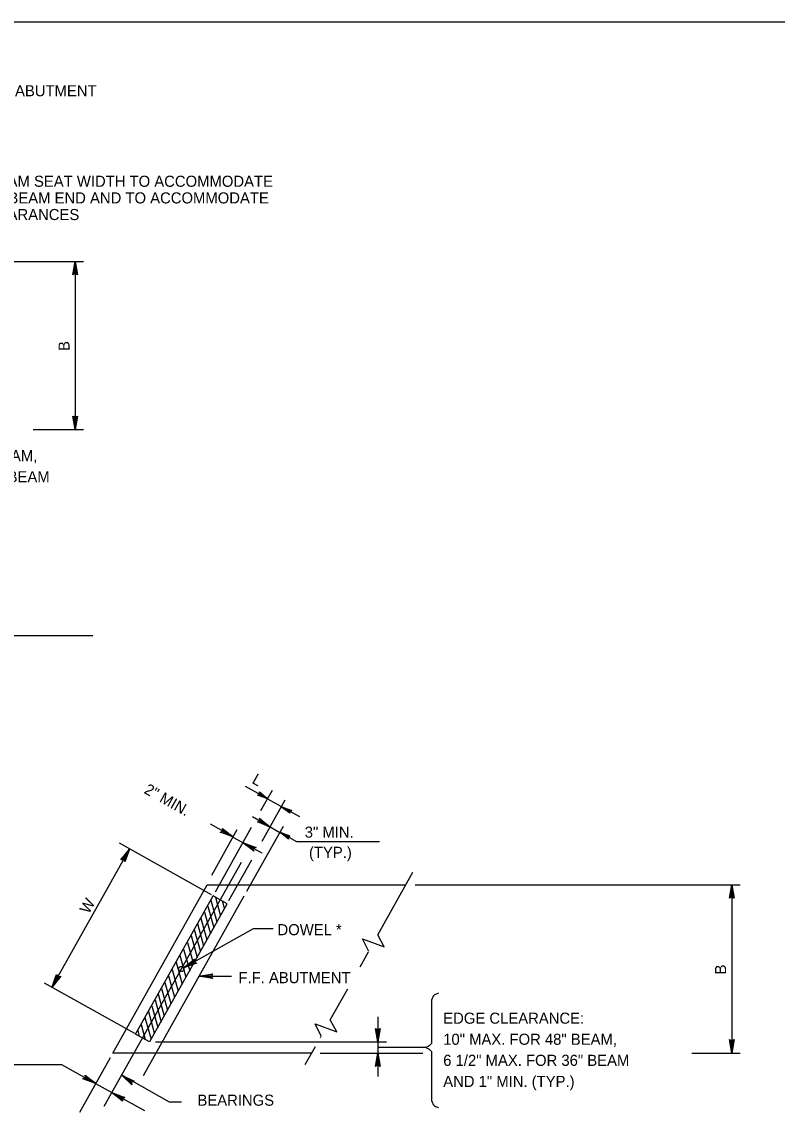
# Model space of a CAD drawing. Extents: x 639028 to 640031, y 298558 to 299746.
# Drawn here: x 639392.4 to 639596.7, y 298842.4 to 299137.3 of the extents above; entities that cross this region are included whole.
import ezdxf

# ---------------------------------------------------------------- set-up
doc = ezdxf.new("R2010")
doc.units = 0
doc.layers.add('1', color=7, linetype='Continuous')

msp = doc.modelspace()

# ---------------------------------------------------------------- linework, layer by layer
at = {"layer": '1'}
for p, q in [((639067.87, 299137.33), (639853.87, 299137.33)), ((639362.68, 299072.53), (639409.1, 299072.53)), ((639406.83, 299072.53), (639406.83, 299027.03)), ((639395.46, 299027.03), (639409.1, 299027.03)), ((639250.86, 298971.38), (639411.63, 298971.38)), ((639458.91, 298927.15), (639452.91, 298930.52)), ((639457.06, 298923.97), (639460.16, 298929.52)), ((639457.4, 298915.71), (639463.66, 298926.9)), ((639458.83, 298927.13), (639467.5, 298922.37)), ((639449.54, 298916.9), (639443.44, 298920.27)), ((639462.17, 298918), (639454.79, 298922.27)), ((639443.79, 298906.52), (639450.66, 298918.9)), ((639444.79, 298902.02), (639454.53, 298919.45)), ((639453.29, 298902.15), (639463.16, 298919.77)), ((639466.79, 298915.52), (639462.16, 298918.15)), ((639443.66, 298901.15), (639418.79, 298915.15)), ((639449.5, 298916.81), (639457.29, 298912.52)), ((639489.11, 298915.52), (639466.79, 298915.52)), ((639400.54, 298876.15), (639421.54, 298913.52)), ((639414.66, 298844.02), (639451.79, 298910.02)), ((639448.41, 298899.65), (639454.56, 298910.63)), ((639488.71, 298890.34), (639498.2, 298907.28)), ((639417.04, 298858.4), (639442.54, 298903.9)), ((639442.54, 298903.9), (639496.3, 298903.9)), ((639498.77, 298903.9), (639586.69, 298903.9)), ((639584.42, 298903.9), (639584.42, 298858.4)), ((639423.16, 298863.52), (639444.16, 298900.9)), ((639425.33, 298852.32), (639452.54, 298900.9)), ((639443.54, 298899.77), (639445.16, 298893.9)), ((639444.16, 298900.9), (639444.29, 298901.02)), ((639447.91, 298898.77), (639444.16, 298900.9)), ((639444.79, 298900.52), (639446.04, 298895.77)), ((639446.66, 298899.4), (639447.16, 298897.52)), ((639427.04, 298861.52), (639447.91, 298898.77)), ((639441.79, 298896.52), (639443.41, 298890.65)), ((639442.66, 298898.15), (639444.29, 298892.27)), ((639439.91, 298893.4), (639441.54, 298887.4)), ((639440.79, 298894.9), (639442.41, 298889.02)), ((639436.13, 298881.47), (639455.03, 298892.06)), ((639439.04, 298891.77), (639440.66, 298886.15)), ((639455.03, 298892.06), (639460.37, 298892.06)), ((639437.16, 298888.27), (639438.79, 298882.4)), ((639438.16, 298890.15), (639439.79, 298884.27)), ((639435.16, 298884.9), (639436.79, 298878.9)), ((639436.16, 298886.52), (639437.79, 298880.65)), ((639483.87, 298881.71), (639486.15, 298885.79)), ((639434.16, 298883.02), (639435.79, 298877.02)), ((639432.04, 298879.27), (639433.66, 298873.52)), ((639433.04, 298881.02), (639434.66, 298875.15)), ((639440.37, 298879.17), (639449.12, 298879.17)), ((639422.91, 298863.65), (639398.54, 298877.27)), ((639430.16, 298875.9), (639431.79, 298870.02)), ((639431.04, 298877.52), (639432.66, 298871.77)), ((639475.83, 298867.37), (639480.55, 298875.78)), ((639428.41, 298872.77), (639430.04, 298866.77)), ((639429.29, 298874.4), (639430.91, 298868.4)), ((639503.38, 298873.18), (639503.22, 298872.72)), ((639503.22, 298872.72), (639503.22, 298860.99)), ((639503.53, 298873.49), (639503.38, 298873.18)), ((639503.69, 298873.8), (639503.53, 298873.49)), ((639503.84, 298873.96), (639503.69, 298873.8)), ((639504, 298874.11), (639503.84, 298873.96)), ((639504.31, 298874.27), (639504, 298874.11)), ((639504.62, 298874.43), (639504.31, 298874.27)), ((639505.08, 298874.58), (639504.62, 298874.43)), ((639427.54, 298871.15), (639429.16, 298865.27)), ((639425.66, 298868.02), (639427.41, 298862.15)), ((639426.66, 298869.65), (639428.16, 298863.9)), ((639488.66, 298868.15), (639488.66, 298861.4)), ((639423.79, 298864.52), (639424.16, 298862.9)), ((639424.66, 298866.15), (639425.79, 298862.02)), ((639426.91, 298861.4), (639423.16, 298863.52)), ((639428.54, 298861.4), (639491.04, 298861.4)), ((639473.17, 298862.61), (639473.35, 298862.94)), ((639488.66, 298861.68), (639488.66, 298852.02)), ((639503.22, 298860.99), (639502.91, 298860.68)), ((639470.8, 298858.4), (639417.04, 298858.4)), ((639469.07, 298855.3), (639471.8, 298860.17)), ((639473.13, 298858.4), (639500.83, 298858.4)), ((639501.66, 298859.9), (639488.66, 298859.9)), ((639502.29, 298860.21), (639501.66, 298859.9)), ((639501.66, 298859.9), (639502.6, 298859.43)), ((639502.6, 298860.36), (639502.29, 298860.21)), ((639502.91, 298860.68), (639502.6, 298860.36)), ((639502.6, 298859.43), (639502.75, 298859.28)), ((639502.75, 298859.28), (639503.06, 298858.97)), ((639503.06, 298858.97), (639503.22, 298858.81)), ((639503.22, 298858.81), (639503.22, 298845.54)), ((639573.64, 298858.4), (639586.69, 298858.4)), ((639403.23, 298855.21), (639333.43, 298855.21)), ((639412.39, 298850.07), (639403.23, 298855.21)), ((639408.04, 298842.4), (639416.41, 298857.15)), ((639432.29, 298845.15), (639419.41, 298852.4)), ((639425.7, 298842.75), (639412.39, 298850.07)), ((639435.54, 298845.15), (639432.29, 298845.15)), ((639503.22, 298845.54), (639503.38, 298845.07)), ((639503.38, 298845.07), (639503.53, 298844.76)), ((639503.53, 298844.76), (639503.69, 298844.45)), ((639503.69, 298844.45), (639503.84, 298844.29)), ((639503.84, 298844.29), (639504, 298844.14)), ((639504, 298844.14), (639504.31, 298843.98)), ((639504.31, 298843.98), (639504.62, 298843.83)), ((639504.62, 298843.83), (639505.08, 298843.67))]:
    msp.add_line(p, q, dxfattribs=at)
for points in [[(639406.45, 299069.03), (639406.58, 299069.15), (639406.83, 299072.53), (639406.45, 299069.03), (639406.2, 299068.9), (639406.83, 299072.53), (639406.95, 299069.15), (639407.2, 299069.03), (639406.83, 299072.53), (639407.45, 299068.9), (639407.2, 299069.03)], [(639407.2, 299030.53), (639407.08, 299030.4), (639406.83, 299027.03), (639407.2, 299030.53), (639407.45, 299030.65), (639406.83, 299027.03), (639406.7, 299030.4), (639406.45, 299030.53), (639406.83, 299027.03), (639406.2, 299030.65), (639406.45, 299030.53)], [(639456.66, 298928.77), (639456.66, 298928.65), (639458.91, 298927.15), (639456.66, 298928.77), (639456.66, 298929.02), (639458.91, 298927.15), (639456.54, 298928.4), (639456.41, 298928.27), (639458.91, 298927.15), (639456.16, 298928.15), (639456.41, 298928.27)], [(639464.91, 298923.4), (639464.91, 298923.65), (639462.66, 298925.02), (639464.91, 298923.4), (639464.91, 298923.27), (639462.66, 298925.02), (639465.04, 298923.9), (639465.16, 298924.02), (639462.66, 298925.02), (639465.41, 298924.02), (639465.16, 298924.02)], [(639456.79, 298921.65), (639456.79, 298921.4), (639459.54, 298919.52), (639456.79, 298921.65), (639456.66, 298921.9), (639459.54, 298919.52), (639456.54, 298921.02), (639456.41, 298920.9), (639459.54, 298919.52), (639456.16, 298920.9), (639456.41, 298920.9)], [(639446.66, 298918.9), (639446.66, 298918.65), (639449.54, 298916.9), (639446.66, 298918.9), (639446.66, 298919.15), (639449.54, 298916.9), (639446.54, 298918.4), (639446.29, 298918.15), (639449.54, 298916.9), (639446.04, 298918.15), (639446.29, 298918.15)], [(639464.41, 298916.52), (639464.41, 298916.65), (639462.16, 298918.15), (639464.41, 298916.52), (639464.54, 298916.27), (639462.16, 298918.15), (639464.54, 298916.9), (639464.79, 298917.02), (639462.16, 298918.15), (639464.91, 298917.15), (639464.79, 298917.02)], [(639455.04, 298913.27), (639455.04, 298913.52), (639452.29, 298915.27), (639455.04, 298913.27), (639455.16, 298913.02), (639452.29, 298915.27), (639455.29, 298913.77), (639455.54, 298914.02), (639452.29, 298915.27), (639455.79, 298914.02), (639455.54, 298914.02)], [(639419.41, 298910.77), (639419.66, 298910.77), (639421.54, 298913.52), (639419.41, 298910.77), (639419.16, 298910.65), (639421.54, 298913.52), (639420.04, 298910.52), (639420.16, 298910.27), (639421.54, 298913.52), (639420.29, 298910.15), (639420.16, 298910.27)], [(639584.04, 298900.4), (639584.17, 298900.52), (639584.42, 298903.9), (639584.04, 298900.4), (639583.79, 298900.27), (639584.42, 298903.9), (639584.54, 298900.52), (639584.79, 298900.4), (639584.42, 298903.9), (639585.04, 298900.27), (639584.79, 298900.4)], [(639486.24, 298885.89), (639484.58, 298889.31), (639490.44, 298887.16), (639488.71, 298890.34)], [(639439.38, 298882.8), (639439.16, 298882.96), (639436.13, 298881.47), (639439.38, 298882.8), (639439.72, 298882.7), (639436.13, 298881.47), (639438.98, 298883.29), (639439.03, 298883.46), (639436.13, 298881.47), (639439.13, 298883.8), (639439.03, 298883.46)], [(639402.66, 298879.02), (639402.41, 298879.02), (639400.54, 298876.15), (639402.66, 298879.02), (639402.91, 298879.15), (639400.54, 298876.15), (639402.04, 298879.15), (639401.91, 298879.4), (639400.54, 298876.15), (639401.79, 298879.65), (639401.91, 298879.4)], [(639443.87, 298878.79), (639443.74, 298879.04), (639440.37, 298879.17), (639443.87, 298878.79), (639443.99, 298878.54), (639440.37, 298879.17), (639443.74, 298879.29), (639443.87, 298879.54), (639440.37, 298879.17), (639443.99, 298879.79), (639443.87, 298879.54)], [(639473.35, 298862.94), (639471.71, 298866.32), (639477.57, 298864.17), (639475.83, 298867.37)], [(639489.04, 298864.9), (639488.91, 298864.77), (639488.66, 298861.4), (639489.04, 298864.9), (639489.29, 298865.02), (639488.66, 298861.4), (639488.54, 298864.77), (639488.29, 298864.9), (639488.66, 298861.4), (639488.04, 298865.02), (639488.29, 298864.9)], [(639584.79, 298861.9), (639584.67, 298861.77), (639584.42, 298858.4), (639584.79, 298861.9), (639585.04, 298862.02), (639584.42, 298858.4), (639584.29, 298861.77), (639584.04, 298861.9), (639584.42, 298858.4), (639583.79, 298862.02), (639584.04, 298861.9)], [(639488.29, 298854.9), (639488.41, 298855.02), (639488.66, 298858.4), (639488.29, 298854.9), (639488.04, 298854.77), (639488.66, 298858.4), (639488.79, 298855.02), (639489.04, 298854.9), (639488.66, 298858.4), (639489.29, 298854.77), (639489.04, 298854.9)], [(639409.54, 298852.27), (639409.54, 298851.9), (639412.41, 298850.15), (639409.54, 298852.27), (639409.54, 298852.4), (639412.41, 298850.15), (639409.41, 298851.65), (639409.16, 298851.52), (639412.41, 298850.15), (639408.91, 298851.4), (639409.16, 298851.52)], [(639422.16, 298850.02), (639422.16, 298850.27), (639419.41, 298852.4), (639422.16, 298850.02), (639422.16, 298849.77), (639419.41, 298852.4), (639422.29, 298850.65), (639422.54, 298850.77), (639419.41, 298852.4), (639422.79, 298850.77), (639422.54, 298850.77)], [(639419.66, 298845.65), (639419.66, 298845.9), (639416.79, 298847.65), (639419.66, 298845.65), (639419.66, 298845.4), (639416.79, 298847.65), (639419.79, 298846.15), (639420.04, 298846.4), (639416.79, 298847.65), (639420.29, 298846.4), (639420.04, 298846.4)]]:
    msp.add_lwpolyline(points, dxfattribs=at)
msp.add_circle((639435.5, 298881.14), 0.704, dxfattribs=at)

# ---------------------------------------------------------------- texts
for s, p in [('F.F. ABUTMENT', (639382.3, 299117.18)), ('INCREASE BEAM SEAT WIDTH TO ACCOMMODATE', (639361.57, 299092.7)), ('SKEW OF P/S BEAM END AND TO ACCOMMODATE', (639361.57, 299088.2)), ('MINIMUM CLEARANCES', (639361.57, 299083.7)), ('10" MAX. FOR 48" BEAM,', (639349.58, 299018.47)), ('6 1/2" MAX. FOR 36" BEAM', (639349.58, 299012.77)), ('3" MIN.', (639468.92, 298916.65)), ('(TYP.)', (639470.06, 298911.18)), ('DOWEL *', (639461.55, 298890.27)), ('F.F. ABUTMENT', (639450.99, 298877.29)), ('EDGE CLEARANCE:', (639506.38, 298866.33)), ('10" MAX. FOR 48" BEAM,', (639506.38, 298860.63)), ('6 1/2" MAX. FOR 36" BEAM', (639506.38, 298854.93)), ('AND 1" MIN. (TYP.)', (639506.38, 298849.23)), ('  BEARINGS', (639437.66, 298844.15))]:
    msp.add_text(s, height=3, dxfattribs=at).set_placement(p)
for s, rotation, p in [('B', 90, (639405.31, 299048.29)), ('L', 330.7111, (639454.41, 298931.52)), ('2" MIN.', 330.7111, (639425.22, 298928.82)), ('W', 60.7111, (639410.48, 298895.82)), ('B', 90, (639582.9, 298879.66))]:
    msp.add_text(s, height=3, rotation=rotation, dxfattribs=at).set_placement(p)

doc.saveas('drawing.dxf')
